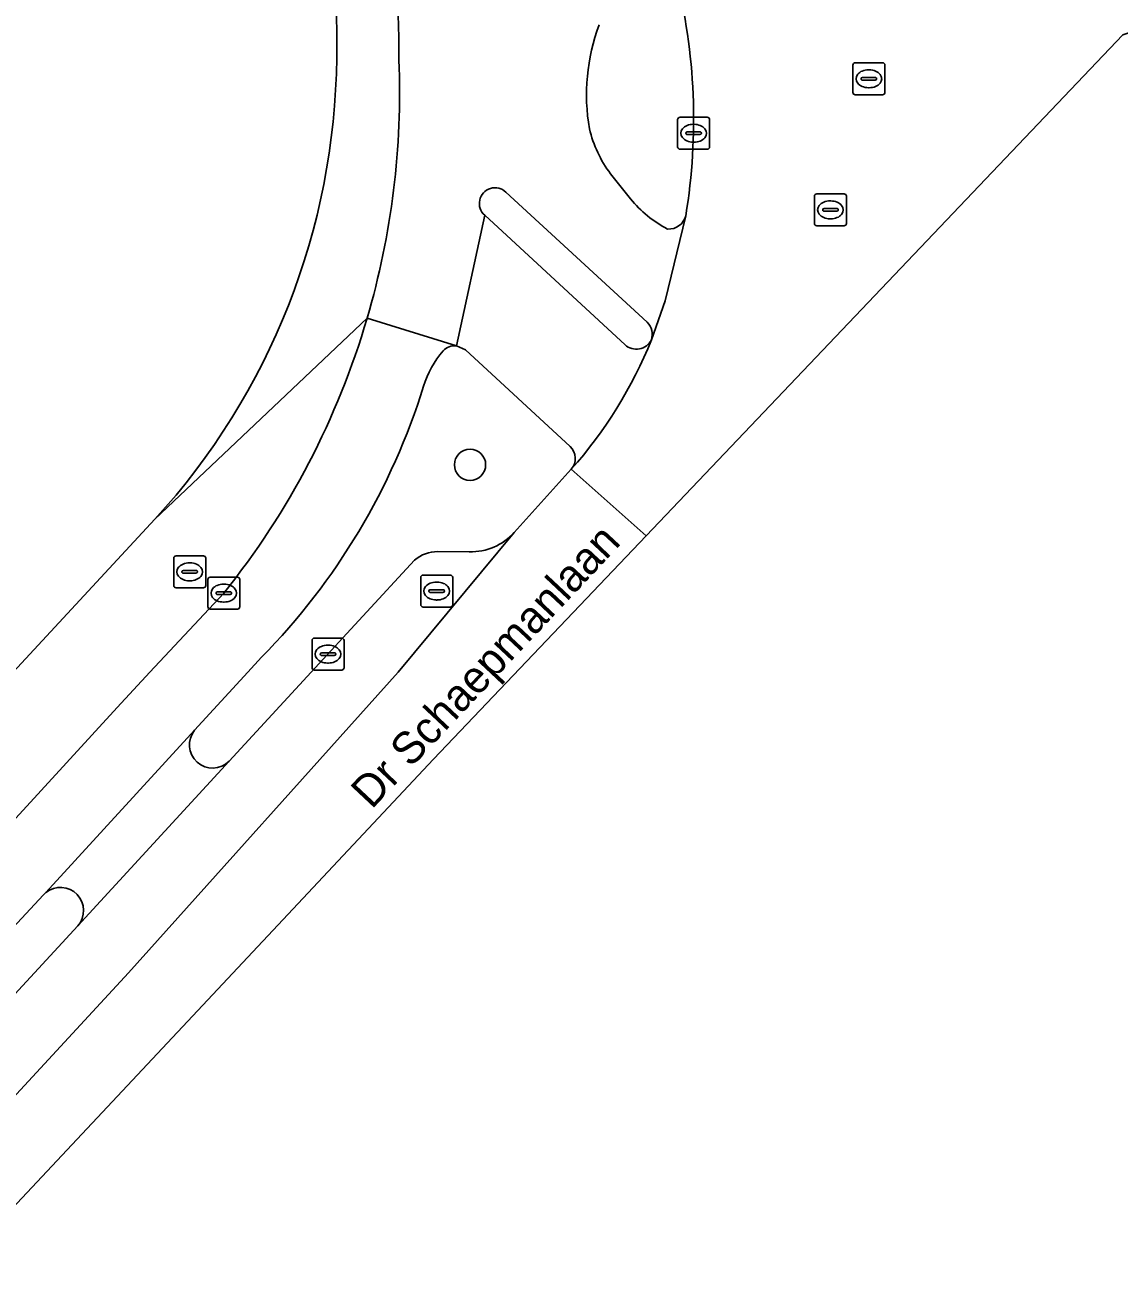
# Model space of a CAD drawing. Extents: x 161347 to 161881, y 382161 to 382804.
# Drawn here: x 161714.84 to 161749.06, y 382231.24 to 382270.25 of the extents above; entities that cross this region are included whole.
import ezdxf

# ---------------------------------------------------------------- set-up
doc = ezdxf.new("R2010")
doc.units = 0
for name, color, linetype in [('IMGEO_Berm_groen', 7, 'Continuous'), ('IMGEO_Boom', 7, 'Continuous'), ('IMGEO_Brandkraan', 7, 'Continuous'), ('IMGEO_Erf', 7, 'Continuous'), ('IMGEO_Fietspad_gesloten', 7, 'Continuous'), ('IMGEO_Fietspad_open', 7, 'Continuous'), ('IMGEO_Kolk', 7, 'Continuous'), ('IMGEO_Openbare_ruimte_label', 7, 'Continuous'), ('IMGEO_Parkeervlak_gesloten', 7, 'Continuous'), ('IMGEO_Rijbaan_lokaal_gesloten', 7, 'Continuous'), ('IMGEO_Rioolput', 7, 'Continuous'), ('IMGEO_Verkeerseiland_open', 7, 'Continuous'), ('IMGEO_Voetpad_open', 7, 'Continuous')]:
    doc.layers.add(name, color=color, linetype=linetype)

msp = doc.modelspace()

# ---------------------------------------------------------------- linework, layer by layer
at = {"layer": 'IMGEO_Berm_groen'}
for points in [[(161731.889, 382257.063), (161728.613, 382260.092), (161728.334, 382260.212)], [(161730.142, 382254.376), (161731.927, 382256.352)], [(161727.751, 382253.776), (161728.736, 382253.77)], [(161721.222, 382247.216), (161723.79, 382250), (161727.024, 382253.505)], [(161722.236, 382250.472), (161721.804, 382250), (161720.143, 382248.188)], [(161715.492, 382243.112), (161715.421, 382243.034), (161704.138, 382230.897)], [(161705.255, 382229.888), (161716.489, 382242.066)]]:
    msp.add_lwpolyline(points, dxfattribs=at)
for centre, radius, start, end in [((161728.279, 382259.724), 0.491, 83.6175, 137.9435), ((161730.311, 382258.01), 3.149, 139.5414, 162.6058), ((161707.305, 382265.155), 20.942, 315.4796, 342.766), ((161731.53, 382256.687), 0.519, 319.7909, 46.3278), ((161728.786, 382255.589), 1.82, 268.4379, 318.1951), ((161727.73, 382252.723), 1.053, 88.8359, 132.0514), ((161720.708, 382247.73), 0.727, 140.9675, 315.0053), ((161715.947, 382242.548), 0.725, 318.3543, 128.8978)]:
    msp.add_arc(centre, radius, start, end, dxfattribs=at)
at = {"layer": 'IMGEO_Boom'}
msp.add_circle((161728.759, 382256.493), 0.489, dxfattribs=at)
at = {"layer": 'IMGEO_Brandkraan'}
for p, q in [((161739.532, 382264.041), (161739.532, 382264.893)), ((161739.607, 382264.967), (161740.459, 382264.967)), ((161740.533, 382264.893), (161740.533, 382264.041)), ((161739.791, 382264.461), (161739.791, 382264.473)), ((161739.834, 382264.51), (161740.232, 382264.51)), ((161740.02, 382264.747), (161740.045, 382264.747)), ((161740.275, 382264.473), (161740.275, 382264.461)), ((161740.229, 382264.424), (161739.831, 382264.424)), ((161740.043, 382264.187), (161740.018, 382264.187)), ((161740.459, 382263.967), (161739.607, 382263.967)), ((161719.49, 382252.717), (161719.49, 382253.569)), ((161719.565, 382253.643), (161720.417, 382253.643)), ((161720.491, 382253.569), (161720.491, 382252.717)), ((161719.749, 382253.137), (161719.749, 382253.149)), ((161719.792, 382253.186), (161720.19, 382253.186)), ((161719.978, 382253.423), (161720.003, 382253.423)), ((161720.233, 382253.149), (161720.233, 382253.137)), ((161720.187, 382253.1), (161719.789, 382253.1)), ((161720.001, 382252.863), (161719.976, 382252.863)), ((161720.417, 382252.643), (161719.565, 382252.643))]:
    msp.add_line(p, q, dxfattribs=at)
for points in [[(161739.532, 382264.041), (161739.532, 382264.893)], [(161739.607, 382264.967), (161740.459, 382264.967)], [(161740.533, 382264.893), (161740.533, 382264.041)], [(161740.459, 382263.967), (161739.607, 382263.967)], [(161719.49, 382252.717), (161719.49, 382253.569)], [(161719.565, 382253.643), (161720.417, 382253.643)], [(161720.491, 382253.569), (161720.491, 382252.717)], [(161720.417, 382252.643), (161719.565, 382252.643)]]:
    msp.add_lwpolyline(points, dxfattribs=at)
for centre, radius, start, end in [((161739.609, 382264.891), 0.0765, 91.552, 178.448), ((161739.609, 382264.891), 0.0765, 91.552, 178.448), ((161740.457, 382264.891), 0.0765, 1.552, 88.448), ((161740.457, 382264.891), 0.0765, 1.552, 88.448), ((161739.831, 382264.47), 0.0403, 85.8775, 175.7526), ((161740.236, 382264.472), 0.0386, 1.7309, 96.639), ((161739.828, 382264.46), 0.0366, 178.938, 274.7102), ((161740.232, 382264.467), 0.043, 264.8664, 352.4533), ((161739.609, 382264.043), 0.0765, 181.552, 268.448), ((161739.609, 382264.043), 0.0765, 181.552, 268.448), ((161740.457, 382264.043), 0.0765, 271.552, 358.448), ((161740.457, 382264.043), 0.0765, 271.552, 358.448), ((161719.567, 382253.567), 0.0765, 91.552, 178.448), ((161719.567, 382253.567), 0.0765, 91.552, 178.448), ((161720.415, 382253.567), 0.0765, 1.552, 88.448), ((161720.415, 382253.567), 0.0765, 1.552, 88.448), ((161719.789, 382253.146), 0.0403, 85.8775, 175.7526), ((161720.194, 382253.148), 0.0386, 1.7309, 96.639), ((161719.786, 382253.136), 0.0366, 178.938, 274.7102), ((161720.19, 382253.143), 0.043, 264.8664, 352.4533), ((161719.567, 382252.719), 0.0765, 181.552, 268.448), ((161719.567, 382252.719), 0.0765, 181.552, 268.448), ((161720.415, 382252.719), 0.0765, 271.552, 358.448), ((161720.415, 382252.719), 0.0765, 271.552, 358.448)]:
    msp.add_arc(centre, radius, start, end, dxfattribs=at)
for centre, major_axis, ratio, start_param, end_param in [((161740.019, 382264.467), (-0.387, 0.002), 0.722429, 4.712389, 7.853982), ((161740.044, 382264.467), (-0.39, 0.002), 0.717154, 1.570796, 4.712389), ((161719.977, 382253.143), (-0.387, 0.002), 0.722429, 4.712389, 7.853982), ((161720.002, 382253.143), (-0.39, 0.002), 0.717154, 1.570796, 4.712389)]:
    msp.add_ellipse(centre, major_axis=major_axis, ratio=ratio, start_param=start_param, end_param=end_param, dxfattribs=at)
at = {"layer": 'IMGEO_Erf'}
msp.add_lwpolyline([(161714.468, 382250), (161718.905, 382254.788)], dxfattribs=at)
for centre, radius, start, end in [((161702.722, 382269.783), 21.873, 358.5238, 55.9857), ((161702.875, 382269.435), 21.714, 317.5804, 359.43)]:
    msp.add_arc(centre, radius, start, end, dxfattribs=at)
at = {"layer": 'IMGEO_Fietspad_gesloten'}
for points in [[(161728.334, 382260.212), (161725.54, 382261.079)], [(161721.055, 382252.476), (161718.748, 382250), (161717.72, 382248.896), (161713.749, 382244.575), (161702.468, 382232.355), (161698.611, 382228.171), (161687.131, 382215.807), (161684.672, 382213.135), (161677.621, 382205.564)], [(161670.585, 382196.187), (161675.538, 382200.57), (161680.121, 382205.08), (161685.018, 382210.269), (161689.615, 382215.176), (161699.491, 382225.854), (161704.138, 382230.897), (161715.421, 382243.034), (161715.492, 382243.112), (161720.143, 382248.188), (161721.804, 382250), (161722.236, 382250.472)]]:
    msp.add_lwpolyline(points, dxfattribs=at)
for centre, radius, start, end in [((161701.554, 382268.113), 24.996, 321.2752, 343.656), ((161728.279, 382259.724), 0.491, 83.6175, 137.9435), ((161730.311, 382258.01), 3.149, 139.5414, 162.6058), ((161707.305, 382265.155), 20.942, 315.4796, 342.766)]:
    msp.add_arc(centre, radius, start, end, dxfattribs=at)
at = {"layer": 'IMGEO_Fietspad_open'}
for points in [[(161733.781, 382264.815), (161733.156, 382265.596)], [(161729.882, 382265.021), (161734.305, 382260.951)], [(161725.54, 382261.079), (161728.334, 382260.212), (161729.218, 382264.298)], [(161734.432, 382260.399), (161734.865, 382261.618), (161735.509, 382264.285)]]:
    msp.add_lwpolyline(points, dxfattribs=at)
for centre, radius, start, end in [((161701.047, 382269.471), 25.49, 359.2963, 49.2134), ((161738.631, 382268.069), 6.229, 159.4877, 189.8564), ((161701.515, 382268.139), 25.041, 343.6249, 2.3329), ((161736.176, 382267.876), 3.784, 193.3393, 217.0551), ((161729.541, 382264.668), 0.491, 45.967, 228.9046), ((161736.573, 382267.042), 3.571, 218.5817, 242.7586), ((161734.972, 382264.42), 0.554, 266.5133, 345.8986), ((161733.922, 382260.572), 0.538, 341.2081, 44.7053)]:
    msp.add_arc(centre, radius, start, end, dxfattribs=at)
at = {"layer": 'IMGEO_Kolk'}
for p, q in [((161735.253, 382266.438), (161735.253, 382267.29)), ((161735.328, 382267.364), (161736.18, 382267.364)), ((161736.254, 382267.29), (161736.254, 382266.438)), ((161735.512, 382266.858), (161735.512, 382266.87)), ((161735.95, 382266.821), (161735.552, 382266.821)), ((161735.555, 382266.907), (161735.953, 382266.907)), ((161735.741, 382267.144), (161735.766, 382267.144)), ((161735.996, 382266.87), (161735.996, 382266.858)), ((161735.764, 382266.584), (161735.739, 382266.584)), ((161736.18, 382266.364), (161735.328, 382266.364)), ((161720.557, 382252.051), (161720.557, 382252.903)), ((161720.632, 382252.977), (161721.484, 382252.977)), ((161721.558, 382252.903), (161721.558, 382252.051)), ((161720.816, 382252.471), (161720.816, 382252.483)), ((161721.254, 382252.434), (161720.856, 382252.434)), ((161720.859, 382252.52), (161721.257, 382252.52)), ((161721.045, 382252.757), (161721.07, 382252.757)), ((161721.3, 382252.483), (161721.3, 382252.471)), ((161721.484, 382251.977), (161720.632, 382251.977)), ((161721.068, 382252.197), (161721.043, 382252.197)), ((161723.817, 382250.143), (161723.817, 382250.995)), ((161723.892, 382251.069), (161724.744, 382251.069)), ((161724.305, 382250.849), (161724.33, 382250.849)), ((161724.818, 382250.995), (161724.818, 382250.143)), ((161724.076, 382250.563), (161724.076, 382250.575)), ((161724.514, 382250.526), (161724.116, 382250.526)), ((161724.119, 382250.612), (161724.517, 382250.612)), ((161724.56, 382250.575), (161724.56, 382250.563)), ((161724.744, 382250.069), (161723.892, 382250.069)), ((161724.328, 382250.289), (161724.303, 382250.289))]:
    msp.add_line(p, q, dxfattribs=at)
for points in [[(161735.253, 382266.438), (161735.253, 382267.29)], [(161735.328, 382267.364), (161736.18, 382267.364)], [(161736.254, 382267.29), (161736.254, 382266.438)], [(161736.18, 382266.364), (161735.328, 382266.364)], [(161720.557, 382252.051), (161720.557, 382252.903)], [(161720.632, 382252.977), (161721.484, 382252.977)], [(161721.558, 382252.903), (161721.558, 382252.051)], [(161721.484, 382251.977), (161720.632, 382251.977)], [(161723.817, 382250.143), (161723.817, 382250.995)], [(161723.892, 382251.069), (161724.744, 382251.069)], [(161724.818, 382250.995), (161724.818, 382250.143)], [(161724.744, 382250.069), (161723.892, 382250.069)]]:
    msp.add_lwpolyline(points, dxfattribs=at)
for centre, radius, start, end in [((161735.33, 382267.288), 0.0765, 91.552, 178.448), ((161735.33, 382267.288), 0.0765, 91.552, 178.448), ((161736.178, 382267.288), 0.0765, 1.552, 88.448), ((161736.178, 382267.288), 0.0765, 1.552, 88.448), ((161735.552, 382266.867), 0.0403, 85.8775, 175.7526), ((161735.549, 382266.857), 0.0366, 178.938, 274.7102), ((161735.953, 382266.864), 0.043, 264.8664, 352.4533), ((161735.957, 382266.869), 0.0386, 1.7309, 96.639), ((161735.33, 382266.44), 0.0765, 181.552, 268.448), ((161735.33, 382266.44), 0.0765, 181.552, 268.448), ((161736.178, 382266.44), 0.0765, 271.552, 358.448), ((161736.178, 382266.44), 0.0765, 271.552, 358.448), ((161720.634, 382252.901), 0.0765, 91.552, 178.448), ((161720.634, 382252.901), 0.0765, 91.552, 178.448), ((161721.482, 382252.901), 0.0765, 1.552, 88.448), ((161721.482, 382252.901), 0.0765, 1.552, 88.448), ((161720.856, 382252.48), 0.0403, 85.8775, 175.7526), ((161720.853, 382252.47), 0.0366, 178.938, 274.7102), ((161721.257, 382252.477), 0.043, 264.8664, 352.4533), ((161721.261, 382252.482), 0.0386, 1.7309, 96.639), ((161720.634, 382252.053), 0.0765, 181.552, 268.448), ((161720.634, 382252.053), 0.0765, 181.552, 268.448), ((161721.482, 382252.053), 0.0765, 271.552, 358.448), ((161721.482, 382252.053), 0.0765, 271.552, 358.448), ((161723.894, 382250.993), 0.0765, 91.552, 178.448), ((161723.894, 382250.993), 0.0765, 91.552, 178.448), ((161724.742, 382250.993), 0.0765, 1.552, 88.448), ((161724.742, 382250.993), 0.0765, 1.552, 88.448), ((161724.116, 382250.572), 0.0403, 85.8775, 175.7526), ((161724.113, 382250.562), 0.0366, 178.938, 274.7102), ((161724.517, 382250.569), 0.043, 264.8664, 352.4533), ((161724.521, 382250.574), 0.0386, 1.7309, 96.639), ((161723.894, 382250.145), 0.0765, 181.552, 268.448), ((161723.894, 382250.145), 0.0765, 181.552, 268.448), ((161724.742, 382250.145), 0.0765, 271.552, 358.448), ((161724.742, 382250.145), 0.0765, 271.552, 358.448)]:
    msp.add_arc(centre, radius, start, end, dxfattribs=at)
for centre, major_axis, ratio, start_param, end_param in [((161735.74, 382266.864), (-0.387, 0.002), 0.722429, 4.712389, 7.853982), ((161735.765, 382266.864), (-0.39, 0.002), 0.717154, 1.570796, 4.712389), ((161721.044, 382252.477), (-0.387, 0.002), 0.722429, 4.712389, 7.853982), ((161721.069, 382252.477), (-0.39, 0.002), 0.717154, 1.570796, 4.712389), ((161724.304, 382250.569), (-0.387, 0.002), 0.722429, 4.712389, 7.853982), ((161724.329, 382250.569), (-0.39, 0.002), 0.717154, 1.570796, 4.712389)]:
    msp.add_ellipse(centre, major_axis=major_axis, ratio=ratio, start_param=start_param, end_param=end_param, dxfattribs=at)
at = {"layer": 'IMGEO_Parkeervlak_gesloten'}
for points in [[(161687.453, 382207.43), (161718.077, 382240.601), (161726.511, 382250), (161730.142, 382254.376)], [(161728.736, 382253.77), (161727.751, 382253.776)], [(161727.024, 382253.505), (161723.79, 382250), (161721.222, 382247.216), (161716.489, 382242.066), (161705.255, 382229.888), (161700.588, 382224.846), (161690.717, 382214.15), (161686.192, 382209.253)]]:
    msp.add_lwpolyline(points, dxfattribs=at)
for centre, radius, start, end in [((161728.786, 382255.589), 1.82, 268.4379, 318.1951), ((161727.73, 382252.723), 1.053, 88.8359, 132.0514)]:
    msp.add_arc(centre, radius, start, end, dxfattribs=at)
at = {"layer": 'IMGEO_Rijbaan_lokaal_gesloten'}
for points in [[(161731.927, 382256.352), (161734.265, 382254.268), (161749.18, 382269.944), (161775.102, 382278.769)], [(161735.509, 382264.285), (161734.865, 382261.618), (161734.432, 382260.399)], [(161623.646, 382164.414), (161647.653, 382173.722), (161675.772, 382191.906), (161706.254, 382224.51), (161727.62, 382247.284), (161734.265, 382254.268), (161731.927, 382256.352), (161730.142, 382254.376), (161726.511, 382250), (161718.077, 382240.601), (161687.453, 382207.43)]]:
    msp.add_lwpolyline(points, dxfattribs=at)
for centre, radius, start, end in [((161717.131, 382267.293), 18.622, 350.7056, 14.1181), ((161721.549, 382265.574), 13.883, 318.3735, 338.1133)]:
    msp.add_arc(centre, radius, start, end, dxfattribs=at)
at = {"layer": 'IMGEO_Rioolput'}
for p, q in [((161740.735, 382268.142), (161740.735, 382268.994)), ((161740.81, 382269.068), (161741.662, 382269.068)), ((161741.223, 382268.848), (161741.248, 382268.848)), ((161741.736, 382268.994), (161741.736, 382268.142)), ((161740.994, 382268.562), (161740.994, 382268.574)), ((161741.432, 382268.525), (161741.034, 382268.525)), ((161741.037, 382268.611), (161741.435, 382268.611)), ((161741.478, 382268.574), (161741.478, 382268.562)), ((161741.662, 382268.068), (161740.81, 382268.068)), ((161741.246, 382268.288), (161741.221, 382268.288)), ((161727.216, 382252.116), (161727.216, 382252.968)), ((161727.291, 382253.042), (161728.143, 382253.042)), ((161727.704, 382252.822), (161727.729, 382252.822)), ((161728.217, 382252.968), (161728.217, 382252.116)), ((161727.475, 382252.536), (161727.475, 382252.548)), ((161727.913, 382252.499), (161727.515, 382252.499)), ((161727.518, 382252.585), (161727.916, 382252.585)), ((161727.959, 382252.548), (161727.959, 382252.536)), ((161728.143, 382252.042), (161727.291, 382252.042)), ((161727.727, 382252.262), (161727.702, 382252.262))]:
    msp.add_line(p, q, dxfattribs=at)
for points in [[(161740.735, 382268.142), (161740.735, 382268.994)], [(161740.81, 382269.068), (161741.662, 382269.068)], [(161741.736, 382268.994), (161741.736, 382268.142)], [(161741.662, 382268.068), (161740.81, 382268.068)], [(161727.216, 382252.116), (161727.216, 382252.968)], [(161727.291, 382253.042), (161728.143, 382253.042)], [(161728.217, 382252.968), (161728.217, 382252.116)], [(161728.143, 382252.042), (161727.291, 382252.042)]]:
    msp.add_lwpolyline(points, dxfattribs=at)
for centre, radius, start, end in [((161740.812, 382268.992), 0.0765, 91.552, 178.448), ((161740.812, 382268.992), 0.0765, 91.552, 178.448), ((161741.66, 382268.992), 0.0765, 1.552, 88.448), ((161741.66, 382268.992), 0.0765, 1.552, 88.448), ((161741.034, 382268.571), 0.0403, 85.8775, 175.7526), ((161741.031, 382268.561), 0.0366, 178.938, 274.7102), ((161741.435, 382268.568), 0.043, 264.8664, 352.4533), ((161741.439, 382268.573), 0.0386, 1.7309, 96.639), ((161740.812, 382268.144), 0.0765, 181.552, 268.448), ((161740.812, 382268.144), 0.0765, 181.552, 268.448), ((161741.66, 382268.144), 0.0765, 271.552, 358.448), ((161741.66, 382268.144), 0.0765, 271.552, 358.448), ((161727.293, 382252.966), 0.0765, 91.552, 178.448), ((161727.293, 382252.966), 0.0765, 91.552, 178.448), ((161728.141, 382252.966), 0.0765, 1.552, 88.448), ((161728.141, 382252.966), 0.0765, 1.552, 88.448), ((161727.515, 382252.545), 0.0403, 85.8775, 175.7526), ((161727.512, 382252.535), 0.0366, 178.938, 274.7102), ((161727.916, 382252.542), 0.043, 264.8664, 352.4533), ((161727.92, 382252.547), 0.0386, 1.7309, 96.639), ((161727.293, 382252.118), 0.0765, 181.552, 268.448), ((161727.293, 382252.118), 0.0765, 181.552, 268.448), ((161728.141, 382252.118), 0.0765, 271.552, 358.448), ((161728.141, 382252.118), 0.0765, 271.552, 358.448)]:
    msp.add_arc(centre, radius, start, end, dxfattribs=at)
for centre, major_axis, ratio, start_param, end_param in [((161741.222, 382268.568), (-0.387, 0.002), 0.722429, 4.712389, 7.853982), ((161741.247, 382268.568), (-0.39, 0.002), 0.717154, 1.570796, 4.712389), ((161727.703, 382252.542), (-0.387, 0.002), 0.722429, 4.712389, 7.853982), ((161727.728, 382252.542), (-0.39, 0.002), 0.717154, 1.570796, 4.712389)]:
    msp.add_ellipse(centre, major_axis=major_axis, ratio=ratio, start_param=start_param, end_param=end_param, dxfattribs=at)
at = {"layer": 'IMGEO_Verkeerseiland_open'}
for points in [[(161733.156, 382265.596), (161733.781, 382264.815)], [(161734.305, 382260.951), (161729.882, 382265.021)], [(161729.218, 382264.298), (161733.607, 382260.242)]]:
    msp.add_lwpolyline(points, dxfattribs=at)
for centre, radius, start, end in [((161717.131, 382267.293), 18.622, 350.7056, 14.1181), ((161738.631, 382268.069), 6.229, 159.4877, 189.8564), ((161736.176, 382267.876), 3.784, 193.3393, 217.0551), ((161729.541, 382264.668), 0.491, 45.967, 228.9046), ((161736.573, 382267.042), 3.571, 218.5817, 242.7586), ((161734.972, 382264.42), 0.554, 266.5133, 345.8986), ((161733.922, 382260.572), 0.538, 341.2081, 44.7053), ((161733.959, 382260.637), 0.529, 228.2667, 333.2828)]:
    msp.add_arc(centre, radius, start, end, dxfattribs=at)
at = {"layer": 'IMGEO_Voetpad_open'}
for points in [[(161733.607, 382260.242), (161729.218, 382264.298), (161728.334, 382260.212), (161728.613, 382260.092), (161731.889, 382257.063)], [(161725.54, 382261.079), (161718.905, 382254.788), (161714.468, 382250), (161684.605, 382217.776), (161678.98, 382211.941)], [(161718.905, 382254.788), (161725.54, 382261.079)], [(161698.611, 382228.171), (161702.468, 382232.355), (161713.749, 382244.575), (161717.72, 382248.896), (161718.748, 382250), (161721.055, 382252.476)], [(161720.143, 382248.188), (161715.492, 382243.112)], [(161716.489, 382242.066), (161721.222, 382247.216)]]:
    msp.add_lwpolyline(points, dxfattribs=at)
for centre, radius, start, end in [((161701.047, 382269.471), 25.49, 359.2963, 49.2134), ((161702.722, 382269.783), 21.873, 358.5238, 55.9857), ((161702.875, 382269.435), 21.714, 317.5804, 359.43), ((161701.515, 382268.139), 25.041, 343.6249, 2.3329), ((161701.554, 382268.113), 24.996, 321.2752, 343.656), ((161721.549, 382265.574), 13.883, 318.3735, 338.1133), ((161733.959, 382260.637), 0.529, 228.2667, 333.2828), ((161731.53, 382256.687), 0.519, 319.7909, 46.3278), ((161720.708, 382247.73), 0.727, 140.9675, 315.0053), ((161715.947, 382242.548), 0.725, 318.3543, 128.8978)]:
    msp.add_arc(centre, radius, start, end, dxfattribs=at)

# ---------------------------------------------------------------- texts
at = {"layer": 'IMGEO_Openbare_ruimte_label'}
msp.add_text('Dr Schaepmanlaan', height=1, rotation=46.8241, dxfattribs=at).set_placement((161725.68, 382245.69))

doc.saveas('drawing.dxf')
